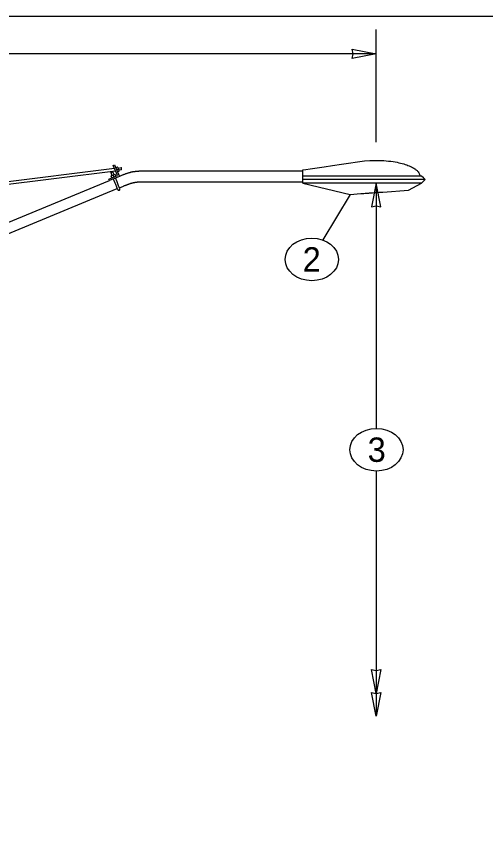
# Model space of a CAD drawing. Extents: x 99862 to 104211, y 98939 to 102076.
# Drawn here: x 101312 to 101620, y 101535 to 102076 of the extents above; entities that cross this region are included whole.
import ezdxf

# ---------------------------------------------------------------- set-up
doc = ezdxf.new("R2010")
doc.units = 0
for name, color, linetype in [('Level 1', 7, 'Continuous'), ('Level 15', 7, 'Continuous'), ('Level 19', 7, 'Continuous'), ('Level 20', 7, 'Continuous'), ('Level 32', 7, 'Continuous'), ('Level 34', 7, 'Continuous'), ('Level 35', 7, 'Continuous'), ('Level 49', 7, 'Continuous'), ('Level 7', 7, 'Continuous')]:
    doc.layers.add(name, color=color, linetype=linetype)

msp = doc.modelspace()

# ---------------------------------------------------------------- linework, layer by layer
at = {"layer": 'Level 1'}
msp.add_lwpolyline([(99862, 99999.5), (103151, 99999.5), (103151, 102075.5), (99862, 102075.5)], close=True, dxfattribs=at)
at = {"layer": 'Level 15'}
for p, q in [((101548.64, 101993.04), (101548.64, 102067.04)), ((101548.64, 102051.04), (101303.47, 102051.04)), ((101548.64, 101966.15), (101548.64, 101805.08)), ((101531.57, 101958.69), (101513.52, 101928.78)), ((101548.64, 101777.08), (101548.64, 101616.02))]:
    msp.add_line(p, q, dxfattribs=at)
for points in [[(101548.64, 102051.04), (101532.92, 102047.96), (101533.65, 102051.04), (101532.92, 102054.13)], [(101548.64, 101966.15), (101545.56, 101950.42), (101548.64, 101951.15), (101551.73, 101950.42)], [(101548.64, 101631.01), (101545.56, 101646.74), (101548.64, 101646.01), (101551.73, 101646.74)], [(101548.64, 101616.02), (101545.56, 101631.74), (101548.64, 101631.01), (101551.73, 101631.74)]]:
    msp.add_lwpolyline(points, close=True, dxfattribs=at)
at = {"layer": 'Level 19'}
for p, q in [((101577.38, 101970.67), (101500.54, 101970.67)), ((101580.78, 101968.41), (101500.54, 101968.41)), ((101578.52, 101970.67), (101577.38, 101970.67)), ((101500.54, 101966.15), (101531.57, 101958.69)), ((101578.52, 101966.15), (101500.54, 101966.15)), ((101569.8, 101961.44), (101578.52, 101966.15)), ((101531.57, 101958.69), (101538.51, 101959.19)), ((101552.96, 101960.23), (101569.8, 101961.44))]:
    msp.add_line(p, q, dxfattribs=at)
for points in [[(101519.92, 101977.63), (101525.88, 101978.51)], [(101525.88, 101978.51), (101541.03, 101980.7)], [(101541.03, 101980.7), (101544.46, 101980.98)], [(101544.46, 101980.98), (101548.64, 101981.04)], [(101500.54, 101974.79), (101502.39, 101975.07)], [(101502.39, 101975.07), (101505.22, 101975.48)], [(101505.22, 101975.48), (101509.92, 101976.17)], [(101509.92, 101976.17), (101514.56, 101976.85)], [(101514.56, 101976.85), (101519.92, 101977.63)], [(101580.78, 101968.41), (101579.65, 101969.54), (101578.52, 101970.67)], [(101578.52, 101966.15), (101579.65, 101967.28), (101580.78, 101968.41)]]:
    msp.add_lwpolyline(points, dxfattribs=at)
for points, degree in [([(101548.64, 101981.04), (101551.17, 101981.04), (101555.41, 101980.83), (101561.28, 101980.03), (101565.95, 101978.99), (101569.7, 101977.75), (101572.58, 101976.42), (101574.48, 101975.22), (101575.87, 101973.97), (101576.69, 101972.95), (101577.23, 101971.8), (101577.37, 101971.06), (101577.38, 101970.67)], 3), ([(101500.54, 101970.58), (101500.54, 101974.79), (101500.54, 101974.79)], 2), ([(101500.54, 101968.41), (101500.54, 101969.17), (101500.54, 101969.92), (101500.54, 101970.67)], 2), ([(101500.54, 101966.15), (101500.54, 101966.9), (101500.54, 101967.65), (101500.54, 101968.41)], 2), ([(101538.51, 101959.19), (101540.34, 101959.32), (101542.12, 101959.45), (101543.82, 101959.57), (101545.73, 101959.71), (101549.29, 101959.97), (101552.96, 101960.23)], 3)]:
    msp.add_open_spline(points, degree=degree, dxfattribs=at)
at = {"layer": 'Level 20'}
for centre in [(101506.37, 101916), (101548.84, 101791.08)]:
    msp.add_ellipse(centre, major_axis=(-17.5, 0), ratio=0.8, dxfattribs=at)
at = {"layer": 'Level 32'}
for p, q in [((101500.16, 101973.93), (101397.22, 101973.93)), ((101060.66, 101838.69), (101373.4, 101967.79)), ((101078.79, 101838.69), (101378.62, 101962.46)), ((101380.06, 101963.06), (101382.64, 101964.12)), ((101397.22, 101967.01), (101500.16, 101967.01))]:
    msp.add_line(p, q, dxfattribs=at)
msp.add_ellipse((101500.16, 101970.47), major_axis=(0, 3.46), ratio=0.000166, start_param=6.283185, end_param=9.424778, dxfattribs=at)
for points in [[(101397.22, 101973.93), (101391.34, 101973.93), (101385.46, 101972.76), (101380.02, 101970.52)], [(101382.64, 101964.12), (101387.25, 101966.03), (101392.24, 101967.01), (101397.22, 101967.01)]]:
    msp.add_open_spline(points, degree=2, dxfattribs=at)
at = {"layer": 'Level 34'}
for p, q in [((101374.27, 101973.01), (101375.1, 101970.98)), ((101376.55, 101971.58), (101375.71, 101973.6)), ((101375.98, 101968.85), (101377.03, 101966.32)), ((101378.47, 101966.92), (101377.43, 101969.45))]:
    msp.add_line(p, q, dxfattribs=at)
for centre, start_param, end_param in [((101374.99, 101973.3), 3.141593, 6.283177), ((101374.99, 101973.3), 6.283177, 6.283185), ((101377.75, 101966.62), 6.283177, 6.283222)]:
    msp.add_ellipse(centre, major_axis=(0.722, 0.298), ratio=0.000371, start_param=start_param, end_param=end_param, dxfattribs=at)
for points in [[(101377.03, 101966.32), (101377.52, 101965.13), (101378.16, 101963.57), (101378.54, 101962.64), (101378.62, 101962.46)], [(101378.62, 101962.46), (101378.74, 101962.14), (101378.83, 101961.92), (101378.85, 101961.88), (101378.99, 101961.61), (101379.45, 101961.32), (101380.13, 101961.52), (101380.4, 101961.98), (101380.32, 101962.4), (101380.29, 101962.49), (101380.24, 101962.62), (101379.63, 101964.11), (101378.76, 101966.22), (101378.47, 101966.92)]]:
    msp.add_open_spline(points, degree=3, dxfattribs=at)
at = {"layer": 'Level 35'}
for p, q in [((101375.92, 101977.7), (101376.89, 101978.1)), ((101376.89, 101978.1), (101380.02, 101970.52)), ((101378.66, 101971.08), (101375.92, 101977.7)), ((101373, 101968.75), (101378.66, 101971.08)), ((101373.4, 101967.79), (101373, 101968.75)), ((101380.02, 101970.52), (101373.4, 101967.79))]:
    msp.add_line(p, q, dxfattribs=at)
at = {"layer": 'Level 49'}
for p, q in [((101376.75, 101975.69), (101000.65, 101928.5)), ((101000.65, 101926.93), (101377.37, 101974.2)), ((101379.12, 101975.99), (101381.23, 101976.26)), ((101381.43, 101974.71), (101379.74, 101974.49))]:
    msp.add_line(p, q, dxfattribs=at)
msp.add_ellipse((101381.33, 101975.48), major_axis=(0.097, -0.775), ratio=0.101579, start_param=6.283177, end_param=9.424785, dxfattribs=at)
at = {"layer": 'Level 7'}
for p, q in [((101378.67, 101976.54), (101377.7, 101976.13)), ((101379.2, 101975.27), (101378.22, 101974.86)), ((101378.75, 101973.59), (101379.72, 101974)), ((101378.87, 101976.59), (101378.84, 101976.61)), ((101379.89, 101974.07), (101379.9, 101974.1)), ((101374.56, 101970.74), (101374.58, 101970.77)), ((101375.04, 101969.59), (101374.63, 101970.57)), ((101375.9, 101971.09), (101376.31, 101970.11)), ((101377.07, 101971.8), (101377.1, 101971.79)), ((101377.17, 101971.61), (101377.58, 101970.64))]:
    msp.add_line(p, q, dxfattribs=at)
for centre, major_axis, ratio, start_param, end_param in [((101379.39, 101975.35), (-0.51, 1.25), 0.000003, 3.226344, 6.283188), ((101375.82, 101971.28), (-1.25, -0.51), 0.000178, 6.282793, 9.424983)]:
    msp.add_ellipse(centre, major_axis=major_axis, ratio=ratio, start_param=start_param, end_param=end_param, dxfattribs=at)
for points, degree in [([(101378.84, 101976.61), (101378.84, 101976.61), (101378.84, 101976.61), (101378.84, 101976.61), (101378.78, 101976.58), (101378.67, 101976.54)], 3), ([(101378.67, 101976.54), (101378.77, 101976.46), (101378.85, 101976.37), (101379, 101976.18), (101379.06, 101976.08), (101379.2, 101975.75), (101379.22, 101975.51), (101379.2, 101975.27)], 3), ([(101379.2, 101975.27), (101379.29, 101975.19), (101379.38, 101975.1), (101379.52, 101974.91), (101379.59, 101974.81), (101379.72, 101974.48), (101379.74, 101974.24), (101379.72, 101974)], 3), ([(101379.72, 101974), (101379.82, 101974.04), (101379.89, 101974.07), (101379.89, 101974.07)], 2), ([(101374.63, 101970.57), (101374.59, 101970.67), (101374.56, 101970.74), (101374.56, 101970.74), (101374.56, 101970.74), (101374.56, 101970.74)], 3), ([(101375.9, 101971.09), (101375.78, 101971.1), (101375.66, 101971.1), (101375.43, 101971.07), (101375.31, 101971.04), (101374.98, 101970.91), (101374.79, 101970.75), (101374.63, 101970.57)], 3), ([(101377.17, 101971.61), (101377.05, 101971.62), (101376.93, 101971.62), (101376.7, 101971.6), (101376.58, 101971.57), (101376.25, 101971.43), (101376.06, 101971.28), (101375.9, 101971.09)], 3), ([(101377.1, 101971.79), (101377.1, 101971.79), (101377.1, 101971.79), (101377.1, 101971.79), (101377.13, 101971.72), (101377.17, 101971.61)], 3)]:
    msp.add_open_spline(points, degree=degree, dxfattribs=at)

# ---------------------------------------------------------------- texts
at = {"layer": 'Level 20'}
for s, p in [('2', (101500.38, 101908)), ('3', (101543.06, 101783.08))]:
    msp.add_text(s, height=16, dxfattribs=at).set_placement(p)

doc.saveas('drawing.dxf')
